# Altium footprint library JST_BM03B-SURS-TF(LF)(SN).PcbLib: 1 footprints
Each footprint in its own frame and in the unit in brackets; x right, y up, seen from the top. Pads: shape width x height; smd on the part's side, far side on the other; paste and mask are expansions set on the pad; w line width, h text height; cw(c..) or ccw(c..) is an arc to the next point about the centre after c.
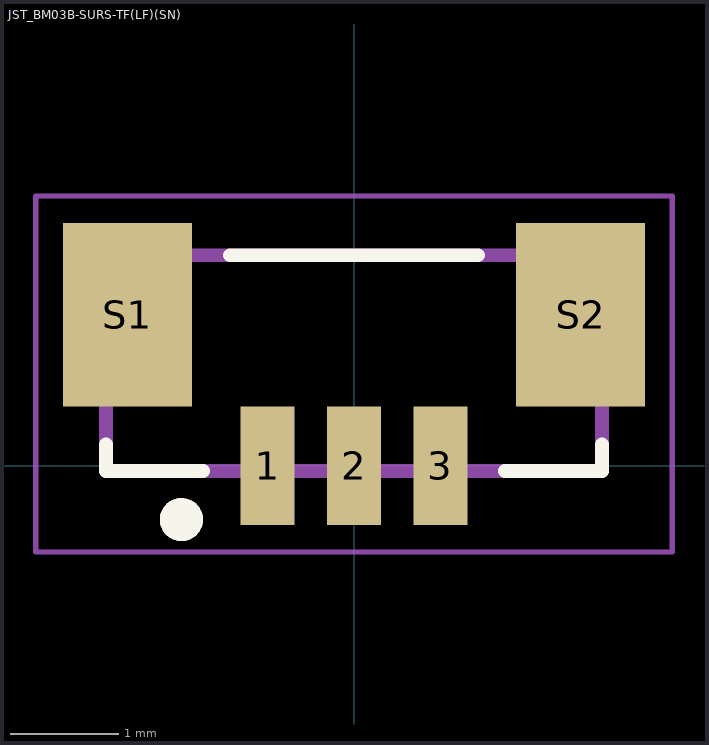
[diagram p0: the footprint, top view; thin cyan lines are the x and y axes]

## JST_BM03B-SURS-TF(LF)(SN) [mm]
height 2.7
pads (5):
  rect 0.5x1.1 smd paste+0 mask+0.102: 1(-0.8,0) 2(0,0) 3(0.8,0)
  rect 1.2x1.7 smd paste+0 mask+0.102: S1(-2.1,1.4) S2(2.1,1.4)
Top Overlay:
  circle w0.2: c-1.6,-0.5 r0.1
  lines w0.127: -2.3,0.2 -2.3,-0.05 -1.4,-0.05 ; -1.15,1.95 1.15,1.95 ; 1.4,-0.05 2.3,-0.05 2.3,0.2
Assembly Top:
  circle w0.2: c-1.6,-0.5 r0.1
  lines w0.127: -2.3,-0.05 -2.3,1.95 2.3,1.95 2.3,-0.05 -2.3,-0.05
Courtyard Top:
  lines w0.05: -2.95,-0.8 -2.95,2.5 2.95,2.5 2.95,-0.8 -2.95,-0.8
3D body "step_temp.STEP": height 2.75, standoff 0, extent -2.3,-0.254 2.3,1.996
